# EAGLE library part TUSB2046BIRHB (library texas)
4-PORT HUB FOR THE UNIVERSAL SERIAL BUS WITH OPTIONAL SERIAL EEPROM INTERFACE Source: http://focus.ti.com/lit/ds/symlink/tusb2046b.pdf
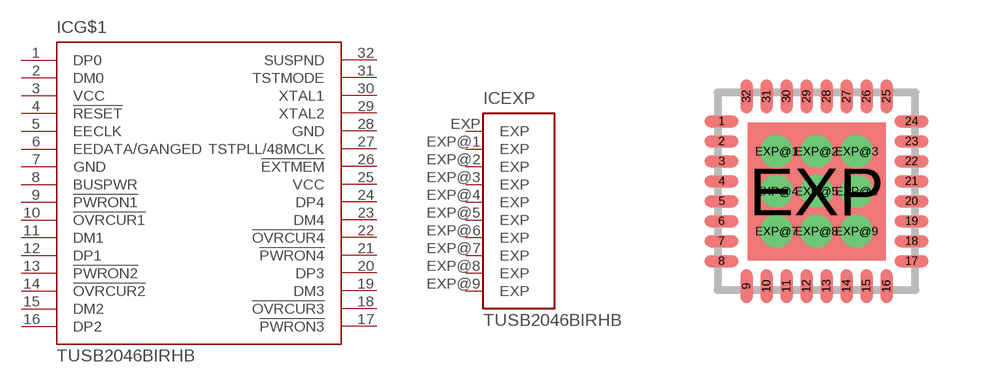
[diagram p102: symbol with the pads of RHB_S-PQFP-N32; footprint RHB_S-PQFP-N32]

Designator prefix IC; gates G$1=TUSB2046B EXP=EXP10

## TUSB2046BIRHBIRHB (MPN: TUSB2046BIRHBT; OC_FARNELL: 1610201; OC_NEWARK: 14N8499)  [RHB_S-PQFP-N32]
1  G$1:DP0
2  G$1:DM0
3  G$1:VCC  pwr
4  G$1:!RESET  in
5  G$1:EECLK  out
6  G$1:EEDATA/GANGED
7  G$1:GND  pwr
8  G$1:BUSPWR  in
9  G$1:!PWRON1  out
10  G$1:!OVRCUR1  in
11  G$1:DM1
12  G$1:DP1
13  G$1:!PWRON2  out
14  G$1:!OVRCUR2  in
15  G$1:DM2
16  G$1:DP2
17  G$1:!PWRON3  out
18  G$1:!OVRCUR3  in
19  G$1:DM3
20  G$1:DP3
21  G$1:!PWRON4  out
22  G$1:!OVRCUR4  in
23  G$1:DM4
24  G$1:DP4
25  G$1:VCC  pwr
26  G$1:!EXTMEM  in
27  G$1:TSTPLL/48MCLK
28  G$1:GND  pwr
29  G$1:XTAL2  out
30  G$1:XTAL1  in
31  G$1:TSTMODE  in
32  G$1:SUSPND  out
EXP  EXP:EXP  pas
EXP@1  EXP:EXP  pas
EXP@2  EXP:EXP  pas
EXP@3  EXP:EXP  pas
EXP@4  EXP:EXP  pas
EXP@5  EXP:EXP  pas
EXP@6  EXP:EXP  pas
EXP@7  EXP:EXP  pas
EXP@8  EXP:EXP  pas
EXP@9  EXP:EXP  pas

## Footprint RHB_S-PQFP-N32 (pad centres in mm)
RHB (S-PQFP-N32) Source: http://focus.ti.com/lit/ds/symlink/tusb2046b.pdf
smd 0.85 x 0.3: 1 -2.375,1.75; 2 -2.375,1.25; 3 -2.375,0.75; 4 -2.375,0.25; 5 -2.375,-0.25; 6 -2.375,-0.75; 7 -2.375,-1.25; 8 -2.375,-1.75; 17 2.375,-1.75; 18 2.375,-1.25; 19 2.375,-0.75; 20 2.375,-0.25; 21 2.375,0.25; 22 2.375,0.75; 23 2.375,1.25; 24 2.375,1.75
smd 0.3 x 0.85: 9 -1.75,-2.375; 10 -1.25,-2.375; 11 -0.75,-2.375; 12 -0.25,-2.375; 13 0.25,-2.375; 14 0.75,-2.375; 15 1.25,-2.375; 16 1.75,-2.375; 25 1.75,2.375; 26 1.25,2.375; 27 0.75,2.375; 28 0.25,2.375; 29 -0.25,2.375; 30 -0.75,2.375; 31 -1.25,2.375; 32 -1.75,2.375
smd 3.45 x 3.45: EXP 0,0
drill 0.3 pad 0.6 round: EXP@1 -1,1; EXP@2 0,1; EXP@3 1,1; EXP@4 -1,0; EXP@5 0,0; EXP@6 1,0; EXP@7 -1,-1; EXP@8 0,-1; EXP@9 1,-1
